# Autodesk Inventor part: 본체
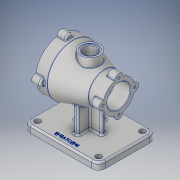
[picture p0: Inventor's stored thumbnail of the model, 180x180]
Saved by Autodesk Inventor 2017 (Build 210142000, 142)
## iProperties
Part Number: 본체
Material: 알루미늄 6061
Document SubType Name: Modeling
Designer: 222
Density: 2.7 g/cm^3
Appearance: 알루미늄 - 평지
Mass: 1049.76 g
Surface Area: 851.002 cm^2
Volume: 388.802 cm^3
Author: 222
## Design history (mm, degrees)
sketch "스케치1"
  geometry: L1 (-50, 0)-(50, 0); L2 (-50, 0)-(-50, 44); L3 (-50, 44)-(-30, 44); L4 (-30, 44)-(25, 27.5); L5 (25, 27.5)-(50, 27.5); L6 (50, 27.5)-(50, 0); 2 further points
  constraints: 12 end point, 2 perpendicular, 1 coincident, 1 horizontal, 1 midpoint, 1 parallel, 1 vertical
  dimensions: "d0" = 100 distance of L1.start L1.end; "d1" = 88 diameter of L3 L1; "d2" = 55 diameter of L5 L1; "d3" = 20 distance of L2.end L3.end; "d4" = 25 distance of L4.end L5.end
revolve "회전1" sketch "스케치1" stored, may be unused: angle "d5" = 90 deg
node "작업 평면1"
sketch "스케치2"
  geometry: L1 (65, 50)-(-65, 50); L2 (-65, 50)-(-65, -50); L3 (-65, -50)-(65, -50); L4 (65, -50)-(65, 50); L5 (65, 50)-(-65, -50); L6 (-65, 50)-(65, -50); 1 further point
  constraints: 12 end point, 2 midpoint, 2 parallel, 1 horizontal, 1 perpendicular
  dimensions: "d7" = 130 distance of L2.end L3.end; "d8" = 100 distance of L1.end L2.end
extrude "돌출1" join sketch "스케치2" distance "d9" = 12; taper "d10" = 0 deg
sketch "스케치3"
  geometry: L1 (-4, -25)-(4, -25); L2 (4, -25)-(4, 25); L3 (4, 25)-(-4, 25); L4 (-4, 25)-(-4, -25); L5 (-4, -25)-(4, 25); L6 (4, -25)-(-4, 25); L7 (-24, 4)-(24, 4); L8 (24, 4)-(24, -4); L9 (24, -4)-(-24, -4); L10 (-24, -4)-(-24, 4); L11 (-24, 4)-(24, -4); L12 (24, 4)-(-24, -4); 1 further point
  constraints: 24 end point, 4 midpoint, 4 parallel, 2 horizontal, 2 perpendicular
  dimensions: "d11" = 8 distance of L2.end L3.end; "d12" = 8 distance of L7.end L8.end; "d13" = 48 distance of L8.end L9.end; "d14" = 50 distance of L3.end L1.start
extrude "돌출2" join sketch "스케치3" stored distance "d15" = 12; taper "d16" = 0 deg
sketch "스케치4"
  geometry: C1 r 17 at (0, 0); 1 further point
  constraints: 1 centre point, 1 coincident
  dimensions: "d17" = 34 diameter of C1
extrude "돌출3" join sketch "스케치4" distance "d18" = 45; taper "d19" = 0 deg
sketch "스케치5"
  geometry: C1 r 14 at (0, 0); 1 further point
  constraints: 1 centre point, 1 coincident
  dimensions: "d20" = 28 diameter of C1
extrude "돌출4" cut sketch "스케치5" distance "d21" = 1; taper "d22" = 0 deg
sketch "스케치6"
  geometry: C1 r 11 at (0, 0); 1 further point
  constraints: 1 centre point, 1 coincident
  dimensions: "d23" = 22 diameter of C1
extrude "돌출5" cut sketch "스케치6" distance "d24" = 44; taper "d25" = 0 deg
sketch "스케치7"
  geometry: C1 r 32 at (0, 0); 1 further point
  constraints: 1 centre point, 1 coincident
  dimensions: "d26" = 64 diameter of C1
extrude "돌출6" cut sketch "스케치7" distance "d27" = 23; taper "d28" = 0 deg
sketch "스케치8"
  geometry: C1 r 26 at (0, 0); 1 further point
  constraints: 1 centre point, 1 coincident
  dimensions: "d29" = 52 diameter of C1
extrude "돌출7" cut sketch "스케치8" distance "d30" = 47; taper "d31" = 0 deg
sketch "스케치9"
  geometry: C1 r 20 at (0, 0); 1 further point
  constraints: 1 centre point, 1 coincident
  dimensions: "d32" = 40 diameter of C1
extrude "돌출8" cut sketch "스케치9" distance "d33" = 30; taper "d34" = 0 deg
sketch "스케치10"
  geometry: L1 (-11, 44)-(11, 44) reference; C1 r 7 at (0, 44); 1 further point
  constraints: 1 centre point, 1 midpoint
  dimensions: "d35" = 14 diameter of C1
extrude "돌출9" join sketch "스케치10" distance "d36" = 15; taper "d37" = 0 deg
sketch "스케치11"
  geometry: C1 r 7 at (0, 27.5); 2 further points
  constraints: 2 vertical alignment, 1 centre point, 1 other
  dimensions: "d41" = 14 diameter of C1
extrude "돌출10" join sketch "스케치11" distance "d42" = 15; taper "d43" = 0 deg
sketch "스케치12"
  geometry: C1 r 32 at (0, -44) reference; A1 r 7 centre (0, 0) between (6.978, -0.557) and (-6.978, -0.557) reference; A2 r 44 centre (0, -44) between (-43.443, -50.978) and (-6.978, -87.443) reference; A3 r 7 centre (0, -88) between (-6.978, -87.443) and (6.978, -87.443) reference; A4 r 44 centre (0, -44) between (6.978, -87.443) and (43.443, -50.978) reference; A5 r 7 centre (44, -44) between (43.443, -50.978) and (43.443, -37.022) reference; A6 r 44 centre (0, -44) between (43.443, -37.022) and (6.978, -0.557) reference; A7 r 7 centre (0, 0) between (6.978, -0.557) and (-6.978, -0.557) reference; A8 r 44 centre (0, -44) between (-6.978, -0.557) and (-43.443, -37.022) reference; A9 r 7 centre (-44, -44) between (-43.443, -37.022) and (-43.443, -50.978) reference; 1 further point
hole "구멍1" sketch "스케치12" at (0, 0), (-44, -44), (0, -88), (44, -44) diameter "d47" = 4.134; stored, may be unused: countersink angle "d51" = 90 deg, drill point angle "d53" = 118 deg; dims "d48" = 9, "d49" = 4, "d50" = 2, "d52" = 11
sketch "스케치13"
  geometry: C1 r 20 at (0, -27.5) reference; A1 r 27.5 centre (0, -27.5) between (-26.609, -34.443) and (-6.943, -54.109) reference; A2 r 7 centre (0, -55) between (-6.943, -54.109) and (6.943, -54.109) reference; A3 r 27.5 centre (0, -27.5) between (6.943, -54.109) and (26.609, -34.443) reference; A4 r 7 centre (27.5, -27.5) between (26.609, -34.443) and (26.609, -20.557) reference; A5 r 27.5 centre (0, -27.5) between (26.609, -20.557) and (6.943, -0.891) reference; A6 r 7 centre (0, 0) between (6.943, -0.891) and (-6.943, -0.891) reference; A7 r 27.5 centre (0, -27.5) between (-6.943, -0.891) and (-26.609, -20.557) reference; A8 r 7 centre (-27.5, -27.5) between (-26.609, -20.557) and (-26.609, -34.443) reference; 1 further point
hole "구멍2" sketch "스케치13" at (0, 0), (-27.5, -27.5), (0, -55), (27.5, -27.5) diameter "d54" = 4.134; stored, may be unused: countersink angle "d58" = 90 deg, drill point angle "d60" = 118 deg; dims "d55" = 9, "d56" = 4, "d57" = 2, "d59" = 11
chamfer "모따기1" distance "d61" = 1; stored, may be unused: second distance "d62" = 2, angle "d63" = 45 deg
fillet "모깎기3" dims "d66" = 3
fillet "모깎기4" dims "d67" = 12
sketch "스케치14"
  geometry: L1 (53, 50)-(-53, 50) reference; L2 (65, -38)-(65, 38) reference; L3 (-53, -50)-(53, -50) reference; L4 (-65, 38)-(-65, -38) reference; C1 r 5 at (-53, 38); C2 r 5 at (-53, -38); C3 r 5 at (53, -38); C4 r 5 at (53, 38); A1 r 12 centre (-53, 38) between (-53, 50) and (-65, 38) reference; A2 r 12 centre (53, 38) between (65, 38) and (53, 50) reference; A3 r 12 centre (53, -38) between (53, -50) and (65, -38) reference; A4 r 12 centre (-53, -38) between (-65, -38) and (-53, -50) reference; 1 further point
  constraints: 4 centre point, 4 coincident
  dimensions: "d68" = 10 diameter of C1; "d69" = 10 diameter of C2; "d70" = 10 diameter of C3; "d71" = 10 diameter of C4
extrude "돌출11" cut sketch "스케치14" stored distance "d72" = 15; taper "d73" = 0 deg
fillet "모깎기5" dims "d74" = 3
fillet "모깎기6" dims "d75" = 3
fillet "모깎기7" dims "d76" = 3
fillet "모깎기8" dims "d77" = 3
fillet "모깎기9" dims "d78" = 3
fillet "모깎기10" dims "d79" = 1
node "작업 평면2"
sketch "스케치15"
  geometry: L1 (-53, -50)-(53, -50) reference; 2 further points
  constraints: 1 vertical alignment, 1 other
  dimensions: "d81" = 10 distance from line of point (0, -40) L1
feature "엠보싱1" sketch "스케치15" dims "d0" = 100, "d1" = 88, "d2" = 55, "d3" = 20, "d4" = 25, "d11" = 8, "d14" = 50, "d82" = 0.5, "d83" = 0
fillet "모깎기11" dims "d84" = 1
node "솔리드1"
pattern_circular "원형 패턴1" dims angle "d39" = 360 deg
pattern_circular "원형 패턴2" dims angle "d45" = 360 deg
node "투영된 루프1"
node "투영된 루프2"
node "투영된 루프3"
other parameters: "d6" = -82, "d80" = 4.75
